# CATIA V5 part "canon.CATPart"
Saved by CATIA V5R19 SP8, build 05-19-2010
Part number: canon
Bounding box of the stored display mesh (mm): x -3 to 98, y -8.5 to 8.5, z -14.268 to 6.25
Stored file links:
  E:\Catia parts\GLOCK\Ensemble culasse\canon.CATPart
  E:\Catia parts\GLOCK\Ensemble culasse\Canon.CATPart
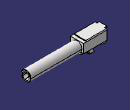
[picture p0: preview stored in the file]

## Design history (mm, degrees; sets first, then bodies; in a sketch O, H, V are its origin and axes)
Body1 (main body)
  Solid1: solid without history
